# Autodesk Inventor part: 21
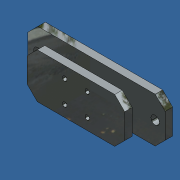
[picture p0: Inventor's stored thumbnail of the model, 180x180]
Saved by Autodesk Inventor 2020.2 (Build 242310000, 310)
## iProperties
Part Number: 21
Material: Generic
Document SubType Name: Modeling
Designer: amoles
Appearance: Zinc
Author: amoles
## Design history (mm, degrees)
feature "Base1"
body "Solid1"
